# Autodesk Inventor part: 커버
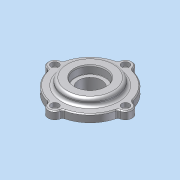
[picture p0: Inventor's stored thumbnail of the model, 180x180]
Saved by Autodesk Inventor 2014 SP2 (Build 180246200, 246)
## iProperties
Company: 한국ATC센터
Created: 2015-03
Part Number: 커버
Document SubType Name: Modeling
Designer: KYOUNG IL JANG
Density: 1 g/cm^3
Material: 일반
Appearance: 기본값
Author: KYOUNG IL JANG
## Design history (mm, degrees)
sketch "스케치1"
  geometry: C1 r 1.621 at (0, 6.75) reference; C2 r 1.621 at (-37, -30.25) reference; C3 r 1.621 at (0, -67.25) reference; C4 r 1.621 at (37, -30.25) reference; C5 r 10 at (0, -30.25) reference; C6 r 12 at (0, -30.25); C7 r 24.5 at (0, -30.25) reference; A1 r 3 centre (-38.77, -20.408) between (-38.239, -23.361) and (-35.862, -21.146) reference; A2 r 7 centre (-37, -30.25) between (-38.239, -23.361) and (-38.239, -37.139) reference; A3 r 3 centre (-38.77, -40.092) between (-35.862, -39.354) and (-38.239, -37.139) reference; A4 r 37 centre (0, -30.25) between (-35.862, -39.354) and (-9.104, -66.113) reference; A5 r 3 centre (-9.842, -69.02) between (-6.889, -68.489) and (-9.104, -66.113) reference; A6 r 7 centre (0, -67.25) between (-6.889, -68.489) and (6.889, -68.489) reference; A7 r 3 centre (9.842, -69.02) between (9.104, -66.112) and (6.889, -68.489) reference; A8 r 37 centre (0, -30.25) between (9.104, -66.112) and (35.863, -39.354) reference; A9 r 3 centre (38.77, -40.092) between (38.239, -37.139) and (35.863, -39.354) reference; A10 r 7 centre (37, -30.25) between (38.239, -37.139) and (38.239, -23.361) reference; A11 r 3 centre (38.77, -20.408) between (35.863, -21.146) and (38.239, -23.361) reference; A12 r 37 centre (0, -30.25) between (35.863, -21.146) and (9.104, 5.612) reference; A13 r 3 centre (9.842, 8.52) between (6.889, 7.989) and (9.104, 5.612) reference; A14 r 7 centre (0, 6.75) between (6.889, 7.989) and (-6.889, 7.989) reference; A15 r 3 centre (-9.842, 8.52) between (-9.104, 5.612) and (-6.889, 7.989) reference; A16 r 37 centre (0, -30.25) between (-9.104, 5.612) and (-35.862, -21.146) reference; 1 further point
  constraints: 1 centre point, 1 coincident
  dimensions: "d2" = 2 radial gap between concentric circles of C6 C5
extrude "돌출1" new body sketch "스케치1" distance "d0" = 8; taper "d1" = 0 deg
sketch "스케치2"
  geometry: C1 r 23.5 at (0, -30.25) reference; C2 r 12 at (0, -30.25) reference; 1 further point
extrude "돌출2" join sketch "스케치2" distance "d4" = 5; taper "d5" = 0 deg
sketch "스케치3"
  geometry: C1 r 23.5 at (0, 0) reference; C2 r 20.5 at (0, 0); 1 further point
  constraints: 1 centre point
  dimensions: "d6" = 3 radial gap between concentric circles of C2 C1
node "작업 평면1"
extrude "돌출3" join sketch "스케치3" stored distance "d7" = 5; taper "d8" = 0 deg
fillet "모깎기1" dims "d9" = 3
sketch "스케치4"
  geometry: C1 r 12 at (0, -30.25) reference; C2 r 27 at (0, -30.25); 1 further point
  constraints: 1 centre point
  dimensions: "d10" = 15 radial gap between concentric circles of C1 C2
extrude "돌출4" join sketch "스케치4" distance "d11" = 7; taper "d12" = 0 deg
fillet "모깎기2" dims "d13" = 3
chamfer "모따기1" distance "d14" = 1; stored, may be unused: second distance "d15" = 2, angle "d16" = 45 deg
node "작업점1"
  node "작업축1"
chamfer "모따기2" distance "d24" = 1; stored, may be unused: second distance "d25" = 2, angle "d26" = 45 deg
hole "구멍6" diameter "d43" = 4.5; stored, may be unused: countersink angle "d47" = 90 deg, drill point angle "d49" = 118 deg; dims "d41" = 10, "d42" = 10, "d44" = 6, "d45" = 8, "d46" = 4.4, "d48" = 8
sketch "스케치8"
  geometry: C1 r 12 at (0, 0) reference; C2 r 16 at (0, 0); 1 further point
  constraints: 1 centre point, 1 coincident
  dimensions: "d53" = 32 diameter of C2
extrude "돌출5" cut sketch "스케치8" distance "d54" = 8.3; taper "d55" = 0 deg
fillet "모깎기3" dims "d56" = 0.3
chamfer "모따기3" distance "d57" = 1.2; stored, may be unused: second distance "d58" = 2, angle "d59" = 30 deg
node "솔리드1"
pattern_circular "원형 패턴1" dims angle "d51" = 360 deg
node "참조1"
node "참조2"
